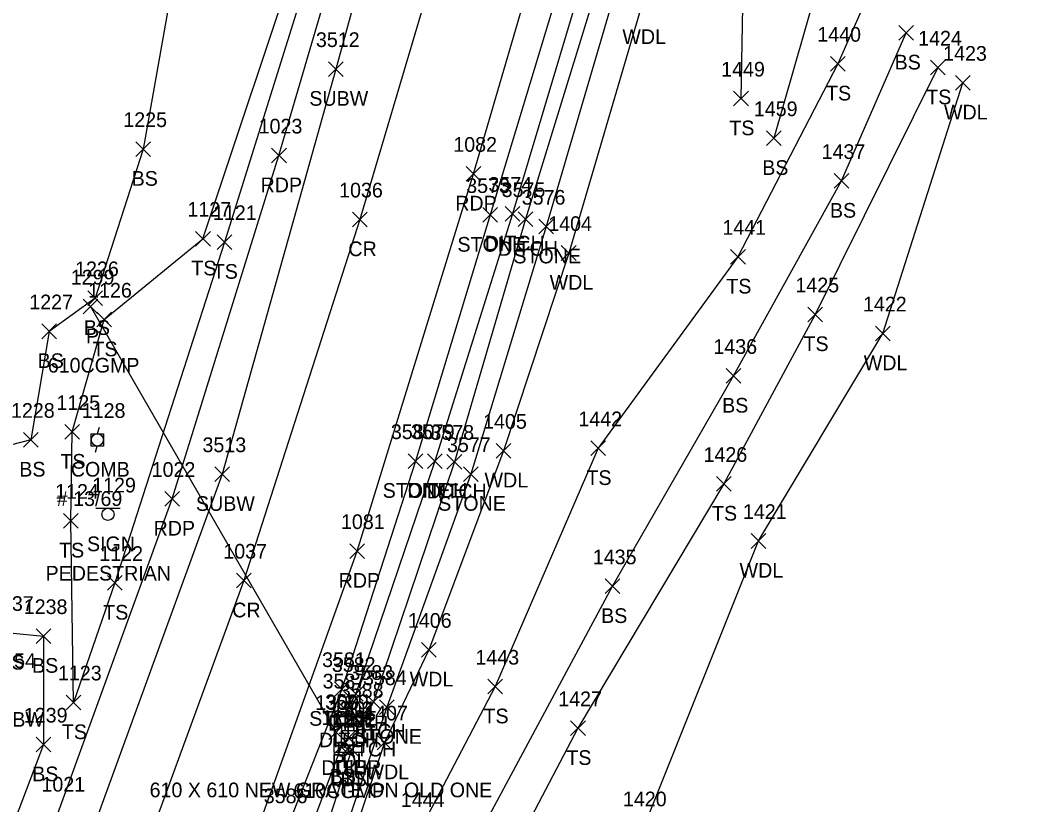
# Model space of a CAD drawing. Extents: x 1634209 to 1639641, y 608564 to 612258.
# Drawn here: x 1639323.4 to 1639460.5, y 611647 to 611753.9 of the extents above; entities that cross this region are included whole.
import ezdxf

# ---------------------------------------------------------------- set-up
doc = ezdxf.new("R2010")
doc.units = 0
for name, color, linetype in [('D_A', 7, 'Continuous'), ('D_C', 7, 'Continuous'), ('D_I', 7, 'Continuous'), ('D_TIC', 7, 'Continuous'), ('DCP', 7, 'Continuous'), ('DD', 7, 'Continuous'), ('DS', 7, 'Continuous'), ('L_A', 7, 'Continuous'), ('L_I', 7, 'Continuous'), ('L_TIC', 7, 'Continuous'), ('LASF', 7, 'Continuous'), ('LAWA', 7, 'Continuous'), ('LELB', 7, 'Continuous'), ('P_A', 7, 'Continuous'), ('P_I', 7, 'Continuous'), ('P_TIC', 7, 'Continuous'), ('PET', 7, 'Continuous'), ('PRC', 7, 'Continuous'), ('S_A', 7, 'Continuous'), ('S_C', 7, 'Continuous'), ('S_I', 7, 'Continuous'), ('SSGN', 7, 'Continuous'), ('U_A', 7, 'Continuous'), ('U_C', 7, 'Continuous'), ('U_I', 7, 'Continuous'), ('U_TIC', 7, 'Continuous'), ('UP', 7, 'Continuous'), ('UW', 7, 'Continuous')]:
    doc.layers.add(name, color=color, linetype=linetype)

msp = doc.modelspace()

# ---------------------------------------------------------------- linework, layer by layer
at = {"layer": 'D_TIC'}
for points in [[(1639389.43, 611726.49), (1639391.43, 611728.49)], [(1639391.43, 611726.49), (1639389.43, 611728.49)], [(1639391.22, 611725.77), (1639393.22, 611727.77)], [(1639393.22, 611725.77), (1639391.22, 611727.77)], [(1639331.98, 611713.86), (1639333.98, 611715.86)], [(1639333.98, 611713.86), (1639331.98, 611715.86)], [(1639378.87, 611692.81), (1639380.87, 611694.81)], [(1639380.87, 611692.81), (1639378.87, 611694.81)], [(1639381.52, 611692.71), (1639383.52, 611694.71)], [(1639383.52, 611692.71), (1639381.52, 611694.71)], [(1639368.1, 611661.09), (1639370.1, 611663.09)], [(1639370.1, 611661.09), (1639368.1, 611663.09)], [(1639370.49, 611660), (1639372.49, 611662)], [(1639372.49, 611660), (1639370.49, 611662)], [(1639366.84, 611658.83), (1639368.84, 611660.83)], [(1639368.84, 611658.83), (1639366.84, 611660.83)], [(1639369.19, 611657.57), (1639371.19, 611659.57)], [(1639371.19, 611657.57), (1639369.19, 611659.57)], [(1639365.43, 611655.9), (1639367.43, 611657.9)], [(1639367.43, 611655.9), (1639365.43, 611657.9)], [(1639367.12, 611655.09), (1639369.12, 611657.09)], [(1639369.12, 611655.09), (1639367.12, 611657.09)], [(1639366.95, 611653.57), (1639368.95, 611655.57)], [(1639368.95, 611653.57), (1639366.95, 611655.57)]]:
    msp.add_lwpolyline(points, dxfattribs=at)
at = {"layer": 'DCP'}
msp.add_lwpolyline([(1639332.98, 611714.86), (1639366.43, 611656.9)], dxfattribs=at)
at = {"layer": 'DD'}
for points in [[(1639560.57, 612129.01), (1639556.53, 612119.06), (1639548.81, 612104.26), (1639529.12, 612083.62), (1639507.53, 612047.31), (1639491.18, 612019.02), (1639473.22, 611983.07), (1639456.59, 611944.52), (1639441.68, 611899.83), (1639426.6, 611855.12), (1639414, 611809.64), (1639403.11, 611769.87), (1639390.43, 611727.49), (1639379.87, 611693.81), (1639369.1, 611662.09), (1639367.84, 611659.83)], [(1639561.94, 612128.14), (1639558.11, 612117.59), (1639549.56, 612103.15), (1639530.32, 612082.73), (1639508.94, 612046.64), (1639492.68, 612018.5), (1639474.74, 611982.05), (1639458.96, 611944.55), (1639442.97, 611899.33), (1639428.64, 611854.96), (1639415.08, 611808.28), (1639405.32, 611769.46), (1639392.22, 611726.77), (1639382.52, 611693.71), (1639371.49, 611661), (1639370.19, 611658.57)]]:
    msp.add_lwpolyline(points, dxfattribs=at)
at = {"layer": 'DS'}
for p, q in [((1639366.18, 611659.01), (1639370.18, 611659.01)), ((1639366.18, 611655.01), (1639366.18, 611659.01)), ((1639370.18, 611659.01), (1639370.18, 611655.01)), ((1639366.16, 611658.09), (1639370.16, 611658.09)), ((1639366.16, 611654.09), (1639366.18, 611658.09)), ((1639367.16, 611657.09), (1639369.16, 611657.09)), ((1639367.16, 611655.09), (1639367.16, 611657.09)), ((1639367.18, 611656.01), (1639367.18, 611658.01)), ((1639367.18, 611658.01), (1639369.18, 611658.01)), ((1639368.18, 611657.01), (1639368.18, 611657.01)), ((1639368.18, 611657.01), (1639368.18, 611657.01)), ((1639369.16, 611657.09), (1639369.16, 611655.09)), ((1639369.18, 611658.01), (1639369.18, 611656.01)), ((1639370.16, 611658.09), (1639370.16, 611654.09)), ((1639369.18, 611656.01), (1639367.18, 611656.01)), ((1639368.17, 611656.1), (1639368.17, 611656.1)), ((1639370.16, 611654.09), (1639366.16, 611654.09)), ((1639370.18, 611655.01), (1639366.18, 611655.01)), ((1639369.16, 611655.09), (1639367.16, 611655.09)), ((1639368.66, 611654.09), (1639369.16, 611654.09))]:
    msp.add_line(p, q, dxfattribs=at)
at = {"layer": 'L_TIC'}
for points in [[(1639443.04, 611751.15), (1639445.04, 611753.15)], [(1639445.04, 611751.15), (1639443.04, 611753.15)], [(1639433.73, 611746.93), (1639435.73, 611748.93)], [(1639435.73, 611746.93), (1639433.73, 611748.93)], [(1639447.38, 611746.41), (1639449.38, 611748.41)], [(1639449.38, 611746.41), (1639447.38, 611748.41)], [(1639450.78, 611744.34), (1639452.78, 611746.34)], [(1639452.78, 611744.34), (1639450.78, 611746.34)], [(1639420.56, 611742.19), (1639422.56, 611744.19)], [(1639422.56, 611742.19), (1639420.56, 611744.19)], [(1639425.01, 611736.79), (1639427.01, 611738.79)], [(1639427.01, 611736.79), (1639425.01, 611738.79)], [(1639339.13, 611735.31), (1639341.13, 611737.31)], [(1639341.13, 611735.31), (1639339.13, 611737.31)], [(1639434.23, 611730.96), (1639436.23, 611732.96)], [(1639436.23, 611730.96), (1639434.23, 611732.96)], [(1639386.4, 611726.33), (1639388.4, 611728.33)], [(1639388.4, 611726.33), (1639386.4, 611728.33)], [(1639394.02, 611724.74), (1639396.02, 611726.74)], [(1639396.02, 611724.74), (1639394.02, 611726.74)], [(1639347.29, 611723.1), (1639349.29, 611725.1)], [(1639349.29, 611723.1), (1639347.29, 611725.1)], [(1639350.21, 611722.64), (1639352.21, 611724.64)], [(1639352.21, 611722.64), (1639350.21, 611724.64)], [(1639397.09, 611721.15), (1639399.09, 611723.15)], [(1639399.09, 611721.15), (1639397.09, 611723.15)], [(1639420.15, 611720.63), (1639422.15, 611722.63)], [(1639422.15, 611720.63), (1639420.15, 611722.63)], [(1639332.62, 611714.99), (1639334.62, 611716.99)], [(1639334.62, 611714.99), (1639332.62, 611716.99)], [(1639430.66, 611712.79), (1639432.66, 611714.79)], [(1639432.66, 611712.79), (1639430.66, 611714.79)], [(1639333.83, 611712.08), (1639335.83, 611714.08)], [(1639335.83, 611712.08), (1639333.83, 611714.08)], [(1639326.33, 611710.48), (1639328.33, 611712.48)], [(1639328.33, 611710.48), (1639326.33, 611712.48)], [(1639439.86, 611710.19), (1639441.86, 611712.19)], [(1639441.86, 611710.19), (1639439.86, 611712.19)], [(1639419.55, 611704.41), (1639421.55, 611706.41)], [(1639421.55, 611704.41), (1639419.55, 611706.41)], [(1639329.46, 611696.77), (1639331.46, 611698.77)], [(1639331.46, 611696.77), (1639329.46, 611698.77)], [(1639323.83, 611695.7), (1639325.83, 611697.7)], [(1639325.83, 611695.7), (1639323.83, 611697.7)], [(1639401.1, 611694.55), (1639403.1, 611696.55)], [(1639403.1, 611694.55), (1639401.1, 611696.55)], [(1639388.22, 611694.21), (1639390.22, 611696.21)], [(1639390.22, 611694.21), (1639388.22, 611696.21)], [(1639376.22, 611692.8), (1639378.22, 611694.8)], [(1639378.22, 611692.8), (1639376.22, 611694.8)], [(1639383.78, 611691.04), (1639385.78, 611693.04)], [(1639385.78, 611691.04), (1639383.78, 611693.04)], [(1639418.2, 611689.7), (1639420.2, 611691.7)], [(1639420.2, 611689.7), (1639418.2, 611691.7)], [(1639329.28, 611684.67), (1639331.28, 611686.67)], [(1639331.28, 611684.67), (1639329.28, 611686.67)], [(1639422.94, 611681.92), (1639424.94, 611683.92)], [(1639424.94, 611681.92), (1639422.94, 611683.92)], [(1639335.29, 611676.21), (1639337.29, 611678.21)], [(1639337.29, 611676.21), (1639335.29, 611678.21)], [(1639403.07, 611675.75), (1639405.07, 611677.75)], [(1639405.07, 611675.75), (1639403.07, 611677.75)], [(1639325.57, 611668.97), (1639327.57, 611670.97)], [(1639327.57, 611668.97), (1639325.57, 611670.97)], [(1639378.03, 611667.1), (1639380.03, 611669.1)], [(1639380.03, 611667.1), (1639378.03, 611669.1)], [(1639366.21, 611661.75), (1639368.21, 611663.75)], [(1639368.21, 611661.75), (1639366.21, 611663.75)], [(1639387.08, 611662.08), (1639389.08, 611664.08)], [(1639389.08, 611662.08), (1639387.08, 611664.08)], [(1639329.67, 611659.93), (1639331.67, 611661.93)], [(1639331.67, 611659.93), (1639329.67, 611661.93)], [(1639372.34, 611659.29), (1639374.34, 611661.29)], [(1639374.34, 611659.29), (1639372.34, 611661.29)], [(1639398.36, 611656.42), (1639400.36, 611658.42)], [(1639400.36, 611656.42), (1639398.36, 611658.42)], [(1639325.59, 611654.19), (1639327.59, 611656.19)], [(1639327.59, 611654.19), (1639325.59, 611656.19)], [(1639366.12, 611653.87), (1639368.12, 611655.87)], [(1639368.12, 611653.87), (1639366.12, 611655.87)], [(1639367.58, 611653.51), (1639369.58, 611655.51)], [(1639369.58, 611653.51), (1639367.58, 611655.51)], [(1639372.01, 611654.47), (1639374.01, 611656.47)], [(1639374.01, 611654.47), (1639372.01, 611656.47)]]:
    msp.add_lwpolyline(points, dxfattribs=at)
at = {"layer": 'LASF'}
for points in [[(1639558.56, 612130.45), (1639552.86, 612120.18), (1639541.01, 612102.18), (1639527.49, 612085.59), (1639505.85, 612048.28), (1639489.98, 612019.2), (1639472.04, 611983.89), (1639455.22, 611944.85), (1639439.42, 611901.14), (1639424.97, 611855.61), (1639411.65, 611810.44), (1639400.31, 611769.99), (1639387.4, 611727.33), (1639377.22, 611693.8), (1639367.21, 611662.75), (1639359.89, 611644.2)], [(1639564.17, 612127.3), (1639559.55, 612115.01), (1639546.48, 612097.15), (1639532.98, 612081.91), (1639511.96, 612045.66), (1639494.66, 612017.18), (1639476.15, 611980.34), (1639460.76, 611943.45), (1639444.67, 611898.59), (1639430.04, 611853.19), (1639417.13, 611807.26), (1639407.25, 611767.41), (1639395.02, 611725.74), (1639384.78, 611692.04), (1639373.34, 611660.29), (1639366.81, 611640.98)]]:
    msp.add_lwpolyline(points, dxfattribs=at)
at = {"layer": 'LAWA'}
msp.add_lwpolyline([(1639441.05, 611876.68), (1639428.25, 611845.92), (1639421.82, 611821.54), (1639414.82, 611793.13), (1639407.98, 611755.62), (1639398.09, 611722.15), (1639389.22, 611695.21), (1639379.03, 611668.1), (1639373.01, 611655.47), (1639368.27, 611641.36), (1639355.32, 611611.85), (1639341.64, 611584.95), (1639331.87, 611563.95), (1639326.04, 611548.05), (1639331.93, 611542.26), (1639351.96, 611561.26), (1639372.68, 611587.74), (1639385.94, 611616.38), (1639408.26, 611643.78), (1639423.94, 611682.92), (1639440.86, 611711.19), (1639451.78, 611745.34)], dxfattribs=at)
at = {"layer": 'LELB'}
for points in [[(1639390.61, 611912.03), (1639380.51, 611879.56), (1639366.54, 611835.06), (1639350.59, 611799.16), (1639345.37, 611765.77), (1639340.13, 611736.31), (1639333.62, 611715.99), (1639327.33, 611711.48), (1639324.83, 611696.7), (1639315.48, 611694.31), (1639319.67, 611684.85)], [(1639396.62, 611874), (1639380.38, 611821.61), (1639366.27, 611771.85), (1639351.21, 611723.64), (1639336.29, 611677.21), (1639330.67, 611660.93), (1639330.28, 611685.67), (1639330.46, 611697.77), (1639334.83, 611713.08), (1639348.29, 611724.1), (1639362.02, 611765.35), (1639371.76, 611802.22), (1639383.1, 611838.36), (1639397.42, 611885.01)], [(1639421.56, 611743.19), (1639421.98, 611765.8), (1639427.91, 611792.5), (1639434.72, 611816.26)], [(1639438.81, 611815.59), (1639435.35, 611786.8), (1639434.37, 611766.94), (1639426.01, 611737.79)], [(1639444.11, 611769.17), (1639434.73, 611747.93), (1639421.15, 611721.63), (1639402.1, 611695.55), (1639388.08, 611663.08), (1639377.92, 611643.68), (1639364.63, 611618.87), (1639351.81, 611603.1), (1639339.53, 611577.73), (1639327.06, 611550.1)], [(1639309.63, 611764.24), (1639299.64, 611734.07), (1639289.6, 611701.48), (1639307.06, 611683.24), (1639321.98, 611670.4), (1639326.57, 611669.97), (1639326.59, 611655.19), (1639316.06, 611627.66)], [(1639328.53, 611549.34), (1639340.68, 611566.19), (1639361.94, 611597.95), (1639384.34, 611640.08), (1639404.07, 611676.75), (1639420.55, 611705.41), (1639435.23, 611731.96), (1639444.04, 611752.15)], [(1639448.38, 611747.41), (1639431.66, 611713.79), (1639419.2, 611690.7), (1639399.36, 611657.42), (1639385.2, 611630.51), (1639376.51, 611608.73)], [(1639319.01, 611537.13), (1639316.51, 611543.95), (1639324.77, 611554.65), (1639337.69, 611583.96), (1639354.16, 611617), (1639362.59, 611636), (1639368.58, 611654.51), (1639367.12, 611654.87), (1639357.8, 611630), (1639344.86, 611601.52), (1639331.86, 611574.07), (1639320.88, 611550.11)]]:
    msp.add_lwpolyline(points, dxfattribs=at)
at = {"layer": 'P_TIC'}
for points in [[(1639357.64, 611734.43), (1639359.64, 611736.43)], [(1639359.64, 611734.43), (1639357.64, 611736.43)], [(1639384.15, 611731.94), (1639386.15, 611733.94)], [(1639386.15, 611731.94), (1639384.15, 611733.94)], [(1639368.66, 611725.72), (1639370.66, 611727.72)], [(1639370.66, 611725.72), (1639368.66, 611727.72)], [(1639343.08, 611687.66), (1639345.08, 611689.66)], [(1639345.08, 611687.66), (1639343.08, 611689.66)], [(1639368.29, 611680.55), (1639370.29, 611682.55)], [(1639370.29, 611680.55), (1639368.29, 611682.55)], [(1639352.84, 611676.52), (1639354.84, 611678.52)], [(1639354.84, 611676.52), (1639352.84, 611678.52)]]:
    msp.add_lwpolyline(points, dxfattribs=at)
at = {"layer": 'PET'}
for points in [[(1639245.26, 611428.04), (1639265.27, 611462.65), (1639285.72, 611496.98), (1639297.96, 611518.63), (1639312.46, 611545.86), (1639331.24, 611585.47), (1639351.91, 611632.95), (1639369.29, 611681.55), (1639385.15, 611732.94), (1639399.72, 611782.78), (1639415.55, 611836.4), (1639431.27, 611887.12), (1639449.51, 611937.71), (1639468.81, 611983.24), (1639484.71, 612016.46), (1639503.95, 612051.42), (1639527.63, 612090.72), (1639556.4, 612135.38), (1639588.32, 612182.52)], [(1639220.96, 611441.47), (1639247.22, 611483.75), (1639268.21, 611519.52), (1639285.57, 611551.38), (1639309.59, 611600.33), (1639328.5, 611645.78), (1639344.08, 611688.66), (1639358.64, 611735.43), (1639372.55, 611782.94), (1639389.96, 611841.92), (1639405.55, 611892.01), (1639422.64, 611939.83), (1639441.75, 611985.91), (1639461.99, 612028.31)]]:
    msp.add_lwpolyline(points, dxfattribs=at)
at = {"layer": 'PRC'}
msp.add_lwpolyline([(1639473.49, 612022.53), (1639453.52, 611981.45), (1639432.7, 611930.67), (1639416.88, 611885.46), (1639401.13, 611834.82), (1639385.48, 611780.16), (1639369.66, 611726.72), (1639353.84, 611677.52), (1639335.57, 611627.61), (1639314.72, 611580.03), (1639292.65, 611536.14), (1639275.3, 611504.78), (1639250.46, 611462.84), (1639222.36, 611418.18)], dxfattribs=at)
at = {"layer": 'SSGN'}
for p, q in [((1639333.7, 611687.38), (1639337.03, 611687.38)), ((1639335.35, 611686.55), (1639335.35, 611686.55))]:
    msp.add_line(p, q, dxfattribs=at)
msp.add_circle((1639335.35, 611686.55), 0.833, dxfattribs=at)
at = {"layer": 'U_TIC'}
for points in [[(1639365.36, 611746.21), (1639367.36, 611748.21)], [(1639367.36, 611746.21), (1639365.36, 611748.21)], [(1639349.92, 611691.02), (1639351.92, 611693.02)], [(1639351.92, 611691.02), (1639349.92, 611693.02)]]:
    msp.add_lwpolyline(points, dxfattribs=at)
at = {"layer": 'UP'}
for p, q in [((1639334.15, 611698.36), (1639333.9, 611697.52)), ((1639333.07, 611695.86), (1639333.07, 611697.52)), ((1639333.07, 611697.52), (1639334.74, 611697.52)), ((1639333.9, 611696.69), (1639333.9, 611696.69)), ((1639334.74, 611697.52), (1639334.74, 611695.86)), ((1639334.74, 611695.86), (1639333.07, 611695.86)), ((1639333.65, 611695.02), (1639333.9, 611695.86))]:
    msp.add_line(p, q, dxfattribs=at)
msp.add_circle((1639333.9, 611696.69), 0.833, dxfattribs=at)
at = {"layer": 'UW'}
msp.add_lwpolyline([(1639594.99, 612226.51), (1639569.63, 612190.35), (1639550.67, 612164.48), (1639527.14, 612128.9), (1639506.92, 612097.5), (1639485.03, 612062.24), (1639463.29, 612024.05), (1639448.18, 611991.92), (1639428.21, 611945.59), (1639409.39, 611896.28), (1639395.47, 611852.57), (1639388.14, 611826.68), (1639366.36, 611747.21), (1639350.92, 611692.02), (1639316.38, 611597.42), (1639292.15, 611550.99), (1639279.15, 611528.72), (1639253.95, 611487.01), (1639229.78, 611449.06), (1639200.46, 611402.5), (1639172.27, 611358.67), (1639148.82, 611320.98)], dxfattribs=at)

# ---------------------------------------------------------------- texts
at = {"layer": 'D_A'}
for s, p in [('DITCH', (1639386.66, 611722.49)), ('DITCH', (1639388.46, 611721.77)), ('P', (1639332.36, 611709.86)), ('DITCH', (1639376.11, 611688.81)), ('DITCH', (1639378.76, 611688.71)), ('DITCH', (1639365.34, 611657.09)), ('DITCH', (1639364.08, 611654.83)), ('DITCH', (1639367.72, 611656)), ('DITCH', (1639366.43, 611653.57)), ('DITHR', (1639364.41, 611651.06)), ('P', (1639365.81, 611651.9)), ('DIB', (1639366.22, 611651.09)), ('DI', (1639367.24, 611652.01)), ('DIIN', (1639365.72, 611649.57))]:
    msp.add_text(s, height=2, dxfattribs=at).set_placement(p)
at = {"layer": 'D_C'}
for s, p in [('610CGMP', (1639327.15, 611705.86)), ('610 X 610 NEW GRATE ON OLD ONE', (1639341.02, 611648.01)), ('610CGMP', (1639360.6, 611647.9))]:
    msp.add_text(s, height=2, dxfattribs=at).set_placement(p)
at = {"layer": 'D_I'}
for s, p in [('3574', (1639387.17, 611730.49)), ('3575', (1639388.96, 611729.77)), ('1299', (1639330.28, 611717.86)), ('3579', (1639376.61, 611696.81)), ('3578', (1639379.26, 611696.71)), ('3582', (1639365.84, 611665.09)), ('3583', (1639368.23, 611664)), ('3587', (1639364.58, 611662.83)), ('3588', (1639366.93, 611661.57)), ('1300', (1639363.58, 611659.9)), ('3589', (1639364.92, 611660.01)), ('1302', (1639365.41, 611659.06)), ('1301', (1639365.91, 611659.09)), ('1291', (1639365.82, 611657.57))]:
    msp.add_text(s, height=2, dxfattribs=at).set_placement(p)
at = {"layer": 'L_A'}
for s, p in [('WDL', (1639405.4, 611750.62)), ('BS', (1639442.48, 611747.15)), ('TS', (1639433.14, 611742.93)), ('TS', (1639446.79, 611742.41)), ('WDL', (1639449.2, 611740.34)), ('TS', (1639419.97, 611738.19)), ('BS', (1639424.45, 611732.79)), ('BS', (1639338.57, 611731.31)), ('BS', (1639433.67, 611726.96)), ('STONE', (1639382.94, 611722.33)), ('STONE', (1639390.56, 611720.74)), ('TS', (1639346.7, 611719.1)), ('TS', (1639349.62, 611718.64)), ('WDL', (1639395.5, 611717.15)), ('TS', (1639419.56, 611716.63)), ('BS', (1639332.06, 611710.99)), ('TS', (1639430.07, 611708.79)), ('TS', (1639333.24, 611708.08)), ('BS', (1639325.77, 611706.48)), ('WDL', (1639438.28, 611706.19)), ('BS', (1639418.99, 611700.41)), ('TS', (1639328.87, 611692.77)), ('BS', (1639323.27, 611691.7)), ('TS', (1639400.51, 611690.55)), ('WDL', (1639386.63, 611690.21)), ('STONE', (1639372.76, 611688.8)), ('STONE', (1639380.32, 611687.04)), ('TS', (1639417.61, 611685.7)), ('TS', (1639328.69, 611680.67)), ('WDL', (1639421.36, 611677.92)), ('TS', (1639334.7, 611672.21)), ('BS', (1639402.51, 611671.75)), ('BS', (1639320.42, 611665.4)), ('BS', (1639325.01, 611664.97)), ('WDL', (1639376.44, 611663.1)), ('FNBW', (1639318.76, 611657.62)), ('STONE', (1639362.75, 611657.75)), ('TS', (1639386.49, 611658.08)), ('TS', (1639329.07, 611655.93)), ('STONE', (1639368.89, 611655.29)), ('TS', (1639397.77, 611652.42)), ('BS', (1639325.03, 611650.19)), ('BS', (1639365.56, 611649.87)), ('BS', (1639367.02, 611649.51)), ('WDL', (1639370.42, 611650.47))]:
    msp.add_text(s, height=2, dxfattribs=at).set_placement(p)
at = {"layer": 'L_I'}
for s, p in [('1440', (1639431.95, 611750.93)), ('1424', (1639445.69, 611750.41)), ('1423', (1639449.09, 611748.34)), ('1449', (1639418.86, 611746.19)), ('1459', (1639423.31, 611740.79)), ('1225', (1639337.44, 611739.31)), ('1437', (1639432.54, 611734.96)), ('3573', (1639384.14, 611730.33)), ('3576', (1639391.7, 611728.74)), ('1127', (1639346.17, 611727.1)), ('1121', (1639349.65, 611726.64)), ('1404', (1639395.31, 611725.15)), ('1441', (1639419.02, 611724.63)), ('1226', (1639330.87, 611718.99)), ('1425', (1639428.97, 611716.79)), ('1126', (1639332.65, 611716.08)), ('1227', (1639324.63, 611714.48)), ('1422', (1639438.17, 611714.19)), ('1436', (1639417.8, 611708.41)), ('1125', (1639328.33, 611700.77)), ('1228', (1639322.14, 611699.7)), ('1405', (1639386.44, 611698.21)), ('1442', (1639399.41, 611698.55)), ('3580', (1639373.88, 611696.8)), ('3577', (1639381.52, 611695.04)), ('1426', (1639416.46, 611693.7)), ('1124', (1639328.16, 611688.67)), ('1421', (1639421.82, 611685.92)), ('1122', (1639334.17, 611680.21)), ('1435', (1639401.38, 611679.75)), ('1237', (1639319.29, 611673.4)), ('1238', (1639323.88, 611672.97)), ('1406', (1639376.2, 611671.1)), ('3581', (1639364.51, 611665.75)), ('1443', (1639385.39, 611666.08)), ('1254', (1639319.59, 611665.62)), ('1123', (1639328.54, 611663.93)), ('3584', (1639370.08, 611663.29)), ('1427', (1639396.67, 611660.42)), ('1239', (1639323.89, 611658.19)), ('1293', (1639364.43, 611657.87)), ('1292', (1639365.88, 611657.51)), ('1407', (1639370.24, 611658.47)), ('3586', (1639356.57, 611647.2)), ('1444', (1639375.23, 611646.68)), ('1420', (1639405.48, 611646.78))]:
    msp.add_text(s, height=2, dxfattribs=at).set_placement(p)
at = {"layer": 'P_A'}
for s, p in [('RDP', (1639356.13, 611730.43)), ('RDP', (1639382.64, 611727.94)), ('CR', (1639368.09, 611721.72)), ('RDP', (1639341.56, 611683.66)), ('RDP', (1639366.77, 611676.55)), ('CR', (1639352.27, 611672.52))]:
    msp.add_text(s, height=2, dxfattribs=at).set_placement(p)
at = {"layer": 'P_I'}
for s, p in [('1023', (1639355.87, 611738.43)), ('1082', (1639382.38, 611735.94)), ('1036', (1639366.83, 611729.72)), ('1022', (1639341.3, 611691.66)), ('1081', (1639367.08, 611684.55)), ('1037', (1639351.06, 611680.52)), ('1021', (1639326.29, 611648.78))]:
    msp.add_text(s, height=2, dxfattribs=at).set_placement(p)
at = {"layer": 'S_A'}
msp.add_text('SIGN', height=2, dxfattribs=at).set_placement((1639332.49, 611681.53))
at = {"layer": 'S_C'}
msp.add_text('PEDESTRIAN', height=2, dxfattribs=at).set_placement((1639326.85, 611677.53))
at = {"layer": 'S_I'}
msp.add_text('1129', height=2, dxfattribs=at).set_placement((1639333.2, 611689.53))
at = {"layer": 'U_A'}
for s, p in [('SUBW', (1639362.77, 611742.21)), ('COMB', (1639330.29, 611691.69)), ('SUBW', (1639347.33, 611687.02))]:
    msp.add_text(s, height=2, dxfattribs=at).set_placement(p)
at = {"layer": 'U_C'}
msp.add_text('# 13/69', height=2, dxfattribs=at).set_placement((1639328.38, 611687.69))
at = {"layer": 'U_I'}
for s, p in [('3512', (1639363.67, 611750.21)), ('1128', (1639331.78, 611699.69)), ('3513', (1639348.22, 611695.02))]:
    msp.add_text(s, height=2, dxfattribs=at).set_placement(p)

doc.saveas('drawing.dxf')
